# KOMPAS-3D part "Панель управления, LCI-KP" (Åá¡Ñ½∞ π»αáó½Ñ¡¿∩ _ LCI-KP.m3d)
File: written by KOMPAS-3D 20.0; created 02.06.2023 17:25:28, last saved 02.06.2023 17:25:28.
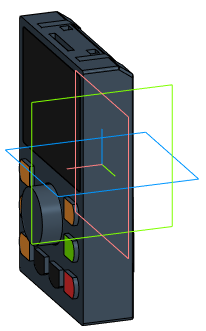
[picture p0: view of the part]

Document properties: Автор: admin; Полное имя файла: P:\INSTART\Технический отдел\ОР\Прочие задачи\КД на номенклатурный ряд\КД на панели управления ПЧ\LCI\Панель управления _ LCI-KP.m3d

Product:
- Part/product: Панель управления  | designation LCI-KP

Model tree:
1. Операция без истории:1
